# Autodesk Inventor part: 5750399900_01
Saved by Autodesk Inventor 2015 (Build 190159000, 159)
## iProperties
Created: 2020-07
Part Number: 5750399900_01
Checked By: TraceParts S.A.
Material: Generic
Catalog Web Link: www.traceparts.com
Document SubType Name: Modeling
Designer: TraceParts
Density: 1 g/cm^3
Appearance: Default
Company: TraceParts S.A.
Author: TraceParts
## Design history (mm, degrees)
feature "5750399900_01.ipt"
body "Solid1"
